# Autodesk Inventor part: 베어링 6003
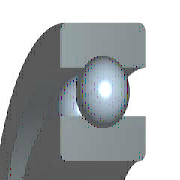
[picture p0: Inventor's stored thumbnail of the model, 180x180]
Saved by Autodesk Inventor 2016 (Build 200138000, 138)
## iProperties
Created: 2012-02
Part Number: 베어링 6003
Material: 강철, 연강
Description: 깊은 그루브 볼 베어링
Document SubType Name: Modeling
Standard: KS B 2023
Designer: mduedu
Standards Organization: KS
Language: ko-KR
Size Designation: 6003 - 17 x 35 x 10
Categories: <MemberInstance><Categories><Category DisplayName="샤프트 부품" InternalName="7f7aeb1f-a693-4053-b835-cee3144e0d98" Mnemonic="SHFT"><Category DisplayName="베어링" Inter
Density: 7.86 g/cm^3
Appearance: 노란색
Mass: 39.0276 g
Surface Area: 48.7538 cm^2
Volume: 4.96535 cm^3
IsCustomPart: 1
Author: mduedu
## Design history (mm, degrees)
sketch "스케치" dims "d0" = 4.68 (= -0.26 x WD + 0.26 x BD)
  geometry: L1 (2.66, 13)-(7.34, 13); L2 (5, 13)-(5, 10.66); L3 (5, 13)-(5, 15.34); L4 (3.261, 11.434)-(0, 11.434); L5 (0, 8.5)-(10, 8.5); L6 (3.261, 14.566)-(0, 14.566); L7 (0, 17.5)-(10, 17.5); L8 (10, 8.5)-(10, 11.434); L9 (6.739, 11.434)-(10, 11.434); L10 (6.739, 14.566)-(10, 14.566); L11 (10, 17.5)-(10, 14.566); L12 (-1.4, 0)-(8.4, 0) reference; L13 (0, -0.3)-(0, 5.3) reference
  constraints: 22 end point, 4 point on line, 2 collinear, 2 perpendicular, 2 symmetric about line, 1 midpoint, 1 parallel, 14 other
  dimensions: "d9" = 17 diameter of L5 L12 (= WD); "d11" = 35 diameter of L7 L12 (= BD); "d12" = 10 distance between parallel lines of L8 L13 (= KB); "d13" = 22.868 diameter of L9 L12 (= 0.326 x BD + 0.674 x WD)
revolve "본체" stored, may be unused: angle "d6" = 90 deg
revolve "볼" stored, may be unused: angle "d7" = 90 deg
pattern_circular "IDS_ARRAYBALL[SIMPL:T]" dims angle "d3" = 360 deg
body "Solid1"
fillet "모깎기1" dims "d1" = 0.3 (= KRS)
other parameters: "WD" = 17 [user parameter; used in 5 equation terms], "BD" = 35 [user parameter; used in 5 equation terms], "KB" = 10 [user parameter; used in 1 equation term], "KRS" = 0.3 [user parameter; used in 1 equation term], "d4" = 0, "d5" = 0, "d8" = 0, "d14" = 0, "d15" = 0, "BBA" = 0 [user parameter], "BC0" = 3250000 [user parameter], "BC" = 6050000 [user parameter], "BR" = 17.5 (= 0.5 x BD) [user parameter], "WR" = 8.5 (= 0.5 x WD) [user parameter]
